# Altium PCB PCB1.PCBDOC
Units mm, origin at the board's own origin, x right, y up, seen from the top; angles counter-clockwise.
Board outline 86 x 56 mm, 2 copper layers (Top Layer, Bottom Layer); 0 components, 0 nets, 0 pads, 0 vias.
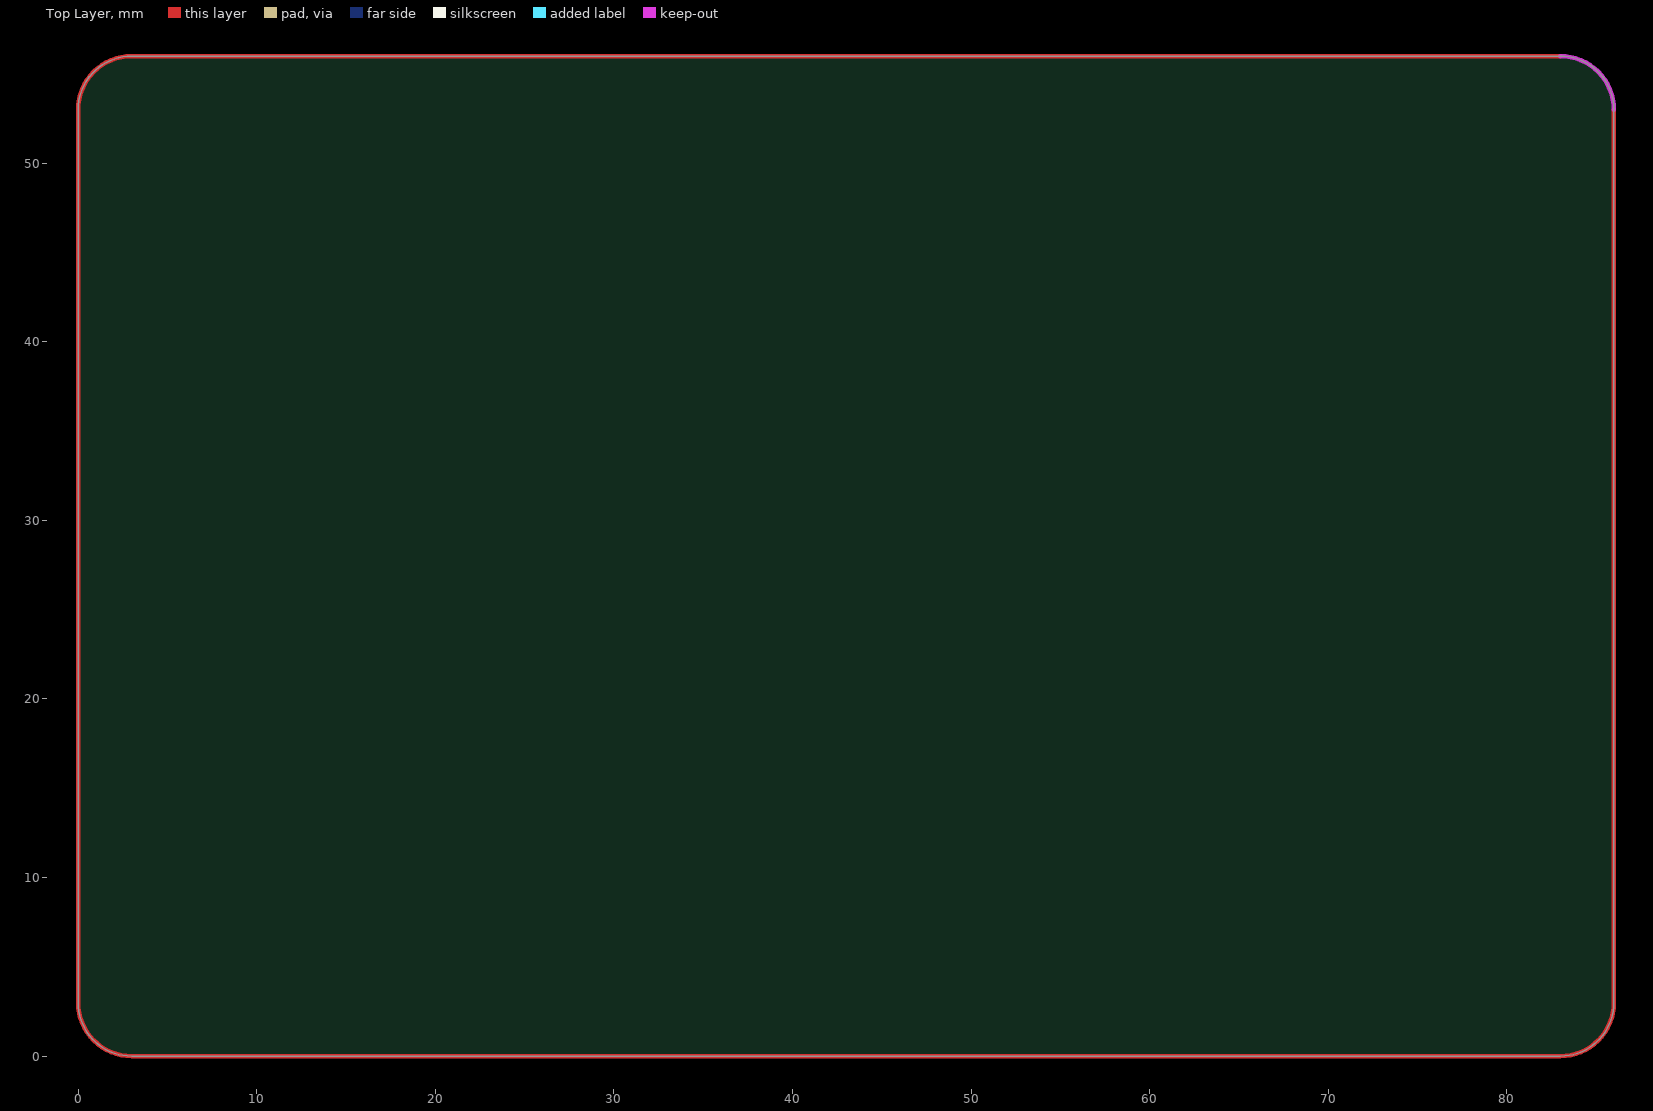
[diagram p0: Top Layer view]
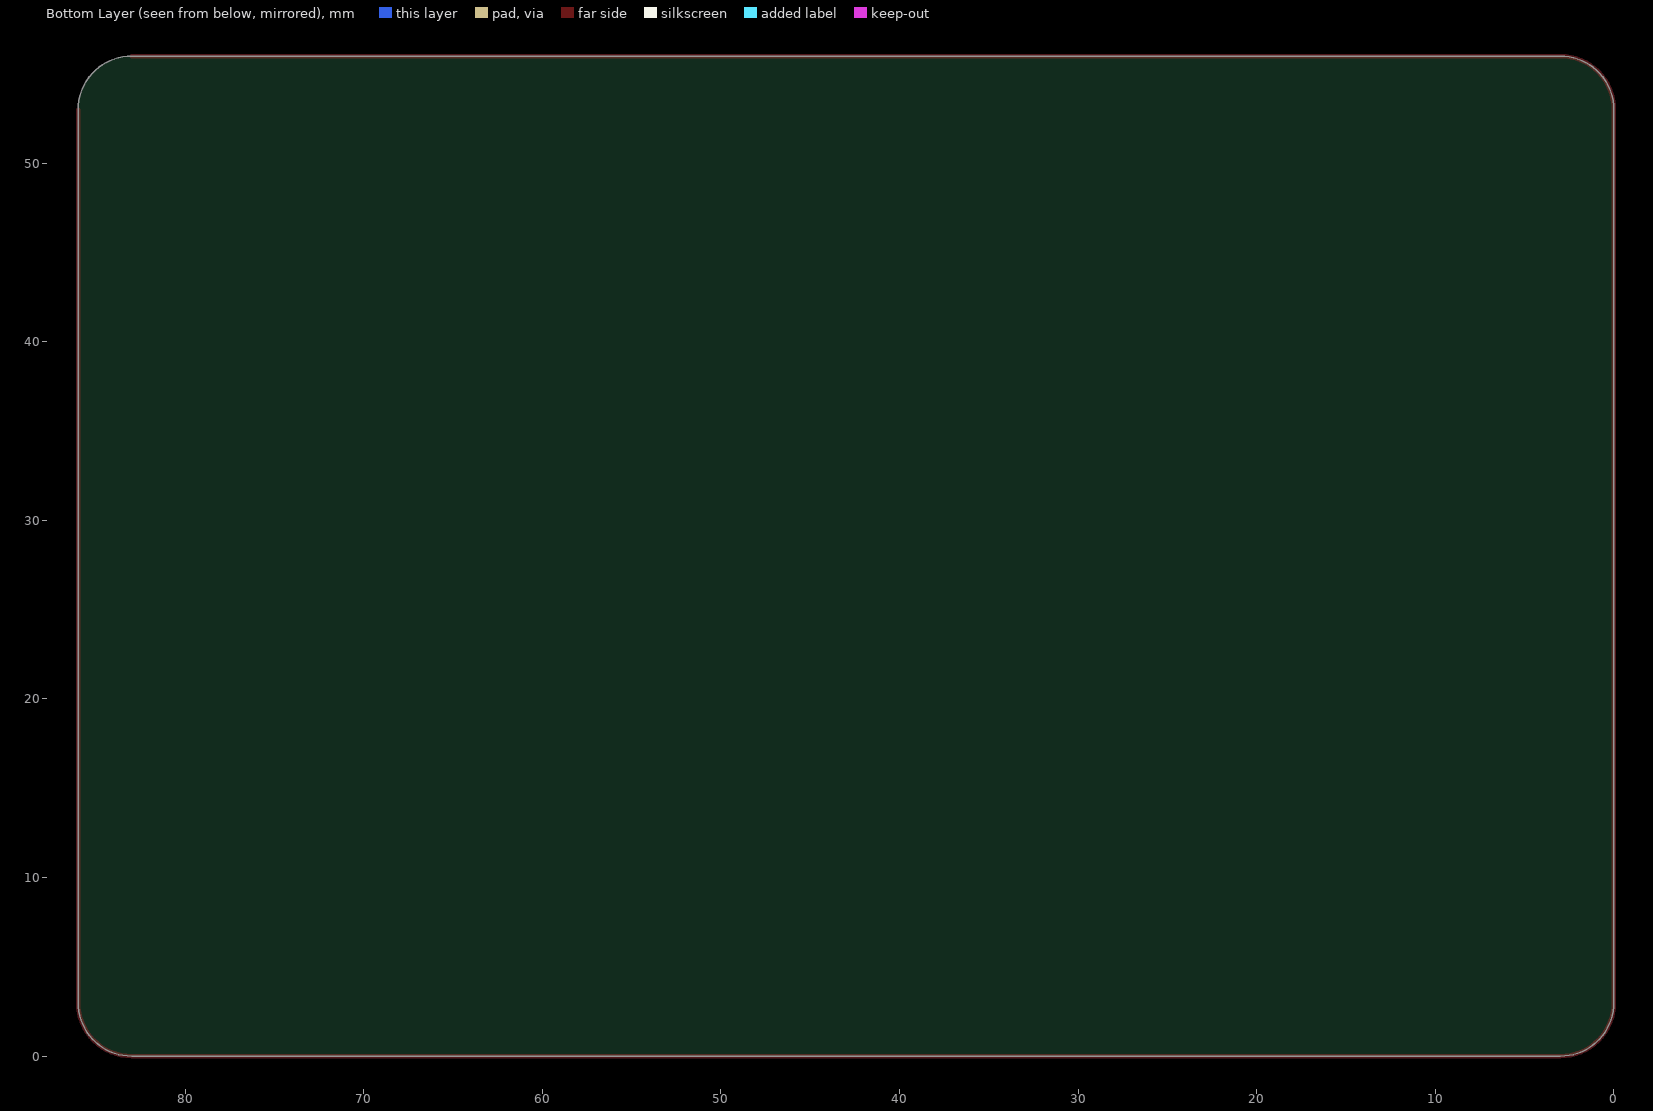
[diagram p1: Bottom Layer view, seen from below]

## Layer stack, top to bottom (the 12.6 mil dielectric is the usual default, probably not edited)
Top Layer: signal copper 0.0356
Dielectric: dielectric 0.32, FR-4, Dk 4.8
Bottom Layer: signal copper 0.0356

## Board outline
0,3 ccw(c3,3) 3,0 83,0 ccw(c83,3) 86,3 86,53 ccw(c83,53) 83,56 3,56 ccw(c3,53) 0,53

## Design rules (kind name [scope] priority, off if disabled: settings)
Clearance [All] p1: gap=0.254
ComponentClearance [All] p1: gap=0.254 collisioncheckmode=3 verticalgap=0.254
PolygonConnect [All] p1: connectstyle=Relief reliefconductorwidth=0.254 reliefentries=4 polygonreliefangle="90 Angle"
RoutingVias [All] p1: holewidth=0.711 width=1.27 viastyle="Through Hole" minholewidth=0.711 minwidth=1.27 maxholewidth=0.711 maxwidth=1.27
SolderMaskExpansion [All] p1: expansion=0.102
TestPointUsage [All] p1: valid=0 allowmultiple=FALSE
Testpoint [All] p1: side=15 testpointundercomponent=TRUE minsize=1.016 maxsize=2.54 preferedsize=1.524 minholesize=0 maxholesize=1.016 preferedholesize=0.813 testpointgrid=0.025 style=1023 order=0123456789
Width [All] p1: maxlimit=0.254 minlimit=0.254 preferedwidth=0.254
18 further rules are at their usual default settings.

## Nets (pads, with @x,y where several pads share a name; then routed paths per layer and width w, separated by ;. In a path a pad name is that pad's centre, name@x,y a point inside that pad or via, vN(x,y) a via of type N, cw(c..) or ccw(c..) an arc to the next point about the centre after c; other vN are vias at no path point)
copper on no net: | length 274.1
  Top Layer w0.254: 83,56 3,56 ccw(c3,53) 0,53 0,3 ccw(c3,3) 3,0 83,0 ccw(c83,3) 86,3 86,53

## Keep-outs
Top Layer:
  lines w0.254: 83,56 cw(c83,53) 86,53

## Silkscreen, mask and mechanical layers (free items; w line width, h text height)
Mechanical 1:
  circle w0.254: c82.75,2.75 r1.25
  circle w0.254: c82.75,53.25 r1.25
  circle w0.254: c62.75,53.25 r1.25
  circle w0.254: c30.25,53.25 r1.25
  circle w0.254: c3.25,53.25 r1.25
  circle w0.254: c3.25,2.75 r1.25
  circle w0.254: c43,33 r1.25
  circle w0.254: c37,15 r1.25
  circle w0.254: c71,33 r1.25
  circle w0.254: c2,47 r1.5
